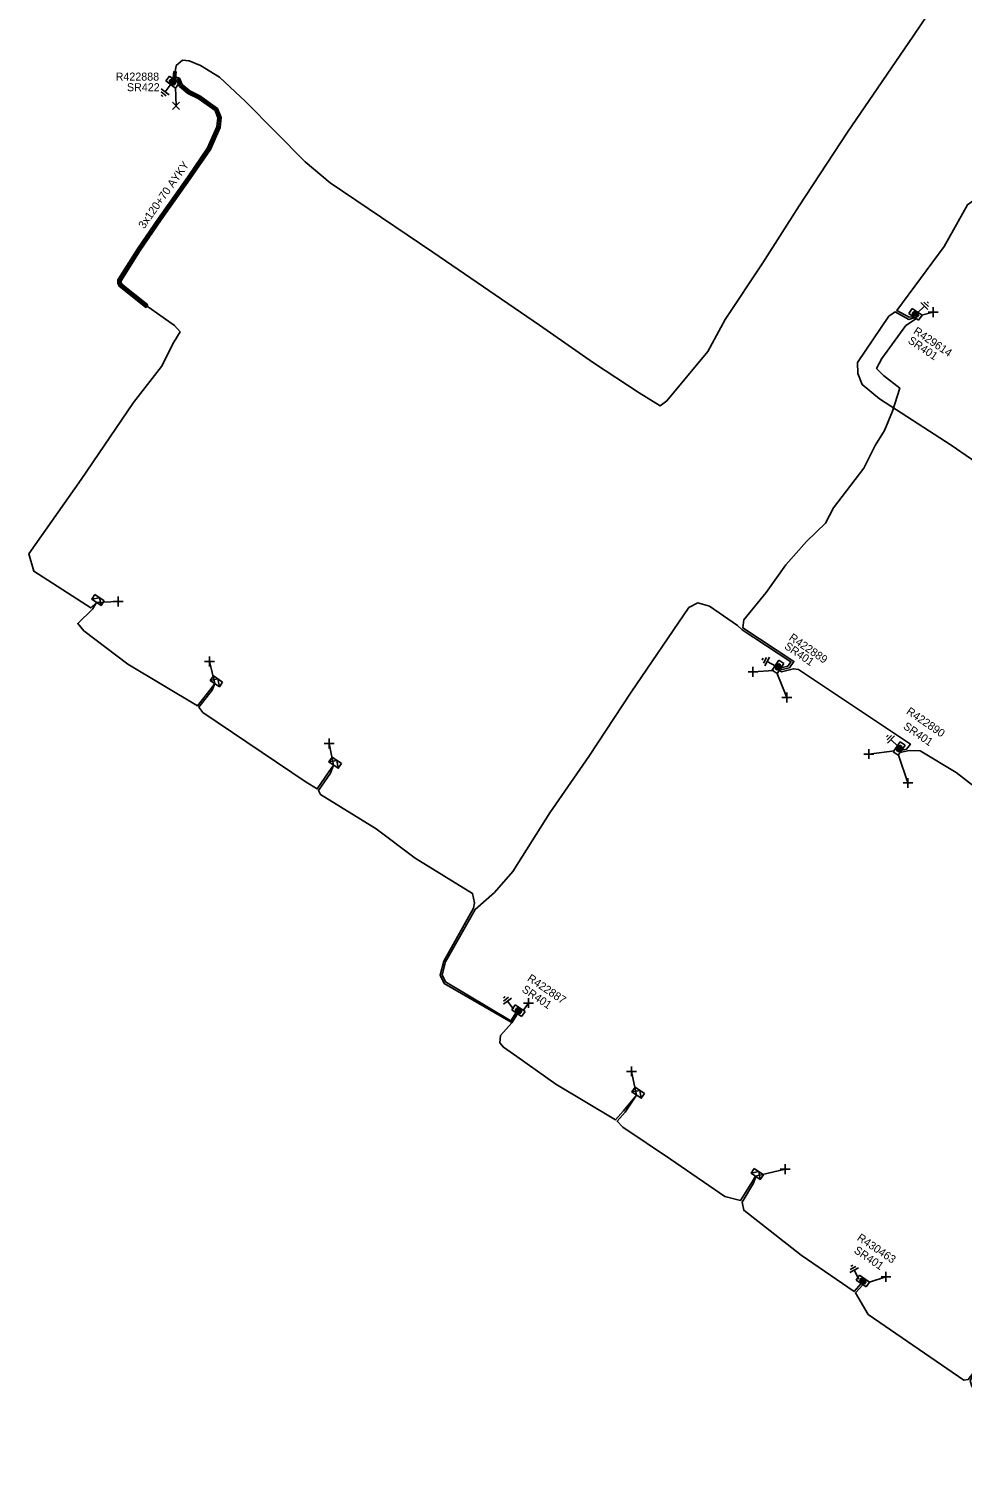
# Model space of a CAD drawing. Extents: x -540247 to -537390, y -1183887 to -1180355.
# Drawn here: x -539012.1 to -538895.4, y -1181471.3 to -1181292.1 of the extents above; entities that cross this region are included whole.
import ezdxf

# ---------------------------------------------------------------- set-up
doc = ezdxf.new("R2010")
doc.units = 0
for name, color, linetype in [('Vrstva 1', 7, 'Continuous'), ('Vrstva 14', 7, 'Continuous'), ('Vrstva 15', 7, 'Continuous'), ('Vrstva 20', 7, 'Continuous'), ('Vrstva 28', 7, 'Continuous'), ('Vrstva 29', 7, 'Continuous'), ('Vrstva 30', 7, 'Continuous'), ('Vrstva 31', 7, 'Continuous'), ('Vrstva 34', 7, 'Continuous'), ('Vrstva 5', 7, 'Continuous'), ('Vrstva 59', 7, 'Continuous'), ('Vrstva 6', 7, 'Continuous'), ('Vrstva 8', 7, 'Continuous'), ('Vrstva 9', 7, 'Continuous')]:
    doc.layers.add(name, color=color, linetype=linetype)

# ---------------------------------------------------------------- blocks, each defined once
blk = doc.blocks.new('NN800')
at = {"layer": 'Vrstva 1'}
for points in [[(-0.44, 0.44), (0.44, -0.44)], [(-0.44, -0.44), (0.44, 0.44)]]:
    blk.add_lwpolyline(points, dxfattribs=at)
blk = doc.blocks.new('NN620')
at = {"layer": 'Vrstva 8'}
for points in [[(0.75, 0), (-0.75, 0)], [(-0.75, 0), (-0.75, -0.75)], [(0.75, -0.75), (0.75, 0)], [(-0.75, -0.75), (0.75, -0.75)], [(0.37, -0.18), (-0.38, -0.18)], [(-0.38, -0.18), (-0.38, -0.56)], [(-0.38, -0.56), (0.37, -0.56)], [(0.32, -0.23), (-0.33, -0.23)], [(-0.33, -0.23), (-0.33, -0.51)], [(-0.33, -0.51), (0.32, -0.51)], [(0.27, -0.27), (-0.28, -0.27)], [(-0.28, -0.27), (-0.28, -0.46)], [(-0.28, -0.46), (0.27, -0.46)], [(0.23, -0.32), (-0.23, -0.32)], [(-0.23, -0.32), (-0.23, -0.42)], [(-0.23, -0.42), (0.23, -0.42)], [(-0.19, -0.37), (0.19, -0.37)], [(0.23, -0.42), (0.23, -0.32)], [(0.27, -0.46), (0.27, -0.27)], [(0.32, -0.51), (0.32, -0.23)], [(0.37, -0.56), (0.37, -0.18)]]:
    blk.add_lwpolyline(points, dxfattribs=at)
blk = doc.blocks.new('NN630')
at = {"layer": 'Vrstva 9'}
for points in [[(0, -0.7), (-0.7, 0)], [(-0.7, -0.7), (-0.7, 0), (0.7, 0), (0.7, -0.7)], [(-0.7, -0.7), (0.7, -0.7)], [(0, -0.7), (0.7, 0)]]:
    blk.add_lwpolyline(points, dxfattribs=at)
blk = doc.blocks.new('NN810')
at = {"layer": 'Vrstva 14'}
for points in [[(0, -0.64), (0, -1.89)], [(0.63, -1.89), (-0.62, -1.89)], [(0.39, -2.2), (-0.4, -2.2)], [(0, -2.52), (-0.12, -2.52)], [(0.14, -2.52), (0, -2.52)]]:
    blk.add_lwpolyline(points, dxfattribs=at)

msp = doc.modelspace()

# ---------------------------------------------------------------- linework, layer by layer
at = {"layer": 'Vrstva 20'}
for points in [[(-538997.22, -1181326.62), (-538997.46, -1181326.94), (-539000.79, -1181324.29), (-539000.97, -1181323.91), (-539000.96, -1181323.49), (-538998.52, -1181319.62), (-538995.88, -1181315.78), (-538993.45, -1181312.31), (-538992.23, -1181310.63), (-538989.75, -1181306.99), (-538988.59, -1181304.36), (-538988.46, -1181303.25), (-538988.82, -1181302.34), (-538990.93, -1181300.81), (-538992.21, -1181300.19), (-538993.25, -1181299.31), (-538993.57, -1181298.62), (-538993.64, -1181298.6), (-538993.69, -1181298.66), (-538994.01, -1181298.42), (-538993.79, -1181298.13), (-538993.27, -1181298.3), (-538992.93, -1181299.07), (-538991.99, -1181299.85), (-538990.73, -1181300.47), (-538988.5, -1181302.08), (-538988.06, -1181303.19), (-538988.19, -1181304.46), (-538989.39, -1181307.19), (-538991.91, -1181310.87), (-538993.13, -1181312.55), (-538995.56, -1181316), (-538998.18, -1181319.84), (-539000.56, -1181323.61), (-539000.57, -1181323.83), (-539000.47, -1181324.03)], [(-538994.13, -1181298.34), (-538994.05, -1181298.22), (-538993.97, -1181297.45), (-538993.67, -1181297.49), (-538993.76, -1181298.33), (-538993.89, -1181298.51)]]:
    msp.add_lwpolyline(points, close=True, dxfattribs=at)
at = {"layer": 'Vrstva 5'}
for points in [[(-538994.01, -1181298.42), (-538993.91, -1181298.28), (-538993.82, -1181297.47), (-538993.66, -1181296.71), (-538992.9, -1181296.02), (-538992.04, -1181296.12), (-538990.64, -1181296.68), (-538988.25, -1181298.17), (-538985.02, -1181301.2), (-538977.55, -1181308.74), (-538974.45, -1181311.38), (-538961.61, -1181320.01), (-538948.29, -1181329.14), (-538941.55, -1181333.87), (-538935.84, -1181337.61), (-538933.19, -1181339.22), (-538932.35, -1181338.61), (-538927.24, -1181332.45), (-538925.06, -1181328.44), (-538920.37, -1181321.36), (-538915.82, -1181314.24), (-538909.77, -1181305.05), (-538901.59, -1181293.05), (-538896.72, -1181285.79)], [(-538876.6, -1181288.05), (-538880.49, -1181293.95), (-538882.71, -1181296.89), (-538882.46, -1181297.61), (-538881.24, -1181298.27), (-538881.1, -1181298.04), (-538881.16, -1181298.59), (-538882.67, -1181297.78), (-538883.26, -1181297.76), (-538887.18, -1181303.5), (-538893.05, -1181311.89), (-538893.15, -1181312.81), (-538891.79, -1181313.26), (-538891.39, -1181313.1), (-538891.78, -1181313.52), (-538893.29, -1181313.03), (-538894.78, -1181314.11), (-538897.72, -1181319.32), (-538903.63, -1181327.31), (-538902.07, -1181328.17), (-538901.52, -1181328.1)], [(-538951.13, -1181415.15), (-538951.82, -1181416.26), (-538960.21, -1181411.42), (-538960.69, -1181410.38), (-538960.25, -1181408.62), (-538956.52, -1181402.03), (-538956.39, -1181401.37), (-538956.63, -1181400.18), (-538963.82, -1181395.78), (-538968.69, -1181392.11), (-538975.65, -1181387.81), (-538975.88, -1181387.32), (-538974.41, -1181385.15), (-538974.01, -1181384.13), (-538974.6, -1181384.98), (-538976.05, -1181387.12), (-538977.45, -1181386.28), (-538990.36, -1181377.56), (-538990.84, -1181376.89), (-538989.17, -1181374.77), (-538988.85, -1181373.95), (-538989.32, -1181374.57), (-538991.02, -1181376.73), (-538999.73, -1181371.54), (-539005.21, -1181367.35), (-539005.98, -1181366.43), (-539004.15, -1181364.66), (-539003.64, -1181363.8), (-539004.35, -1181364.5), (-539011.47, -1181359.91), (-539012.11, -1181357.73), (-539005.57, -1181348.42), (-538999, -1181338.81), (-538995.51, -1181334.33), (-538993.97, -1181331.26), (-538993.18, -1181329.98), (-538993.89, -1181329.18), (-538997.14, -1181326.92), (-538997.34, -1181326.78), (-539000.63, -1181324.16), (-539000.77, -1181323.87), (-539000.76, -1181323.55), (-538998.35, -1181319.73), (-538995.72, -1181315.89), (-538993.29, -1181312.43), (-538992.07, -1181310.75), (-538989.57, -1181307.09), (-538988.39, -1181304.41), (-538988.26, -1181303.22), (-538988.66, -1181302.21), (-538990.83, -1181300.64), (-538992.1, -1181300.02), (-538993.09, -1181299.19), (-538993.42, -1181298.46), (-538993.72, -1181298.36), (-538993.85, -1181298.54)], [(-538918.17, -1181372.07), (-538917.99, -1181372.2), (-538917.05, -1181371.97), (-538916.48, -1181371.17), (-538922.88, -1181366.99), (-538922.74, -1181366), (-538919.96, -1181362.56), (-538917.5, -1181359.1), (-538914.93, -1181356.19), (-538912.52, -1181353.91), (-538911.52, -1181351.97), (-538907.74, -1181347.01), (-538906.34, -1181344.2), (-538905.18, -1181342.3), (-538904.16, -1181339.91), (-538903.26, -1181337.02), (-538905.31, -1181335.43), (-538906.16, -1181334.56), (-538905.52, -1181333.32), (-538902.49, -1181329.2), (-538901.18, -1181328.32)], [(-538901.35, -1181328.21), (-538902.12, -1181328.43), (-538903.82, -1181327.49), (-538904.61, -1181328.02), (-538908.52, -1181333.8), (-538908.51, -1181335.18), (-538907.95, -1181336.57), (-538905.78, -1181338.37), (-538896.83, -1181344.13), (-538889.35, -1181349.32), (-538885.03, -1181352.64), (-538880.81, -1181353.87), (-538878.18, -1181356.19), (-538876.84, -1181356.64), (-538875.59, -1181355.58), (-538871.8, -1181350.1), (-538870.87, -1181350.27), (-538869.79, -1181350.73), (-538869.04, -1181350.41)], [(-538951.23, -1181415.08), (-538951.86, -1181416.09), (-538960.01, -1181411.24), (-538960.43, -1181410.36), (-538960.01, -1181408.72), (-538956.31, -1181402.17), (-538953.92, -1181400.07), (-538951.63, -1181397.45), (-538946.98, -1181390.11), (-538942.12, -1181383.05), (-538936.81, -1181375.02), (-538929.62, -1181364.45), (-538928.48, -1181363.86), (-538927.02, -1181364.29), (-538923.53, -1181366.7), (-538922.97, -1181367.23), (-538916.86, -1181371.22), (-538917.25, -1181371.77), (-538917.94, -1181371.93), (-538918.02, -1181371.87)], [(-538918.31, -1181372.28), (-538918.04, -1181372.47), (-538916.55, -1181372.1), (-538915.9, -1181372.18), (-538901.93, -1181381.51), (-538902.41, -1181382.13), (-538903.02, -1181382.27)], [(-538903.23, -1181382.58), (-538902.08, -1181382.3), (-538900.71, -1181382.36), (-538896.23, -1181385.05), (-538890.51, -1181389.46), (-538887.34, -1181391.55), (-538887.48, -1181392.31), (-538888.12, -1181392.32)], [(-538908.07, -1181448.94), (-538908.97, -1181449.93), (-538915.6, -1181445.37), (-538922.76, -1181439.78), (-538922.97, -1181438.76), (-538921.52, -1181436.37), (-538921.25, -1181435.55), (-538921.27, -1181435.52), (-538921.71, -1181436.23), (-538923.14, -1181438.55), (-538925.13, -1181438.06), (-538931.91, -1181433.37), (-538937.87, -1181429.37), (-538938.59, -1181428.63), (-538937.57, -1181427.5), (-538936.15, -1181425.38), (-538936.15, -1181425.37), (-538937.76, -1181427.34), (-538938.79, -1181428.46), (-538946.25, -1181424.02), (-538951.11, -1181420.54), (-538952.79, -1181419.39), (-538953.23, -1181418.85), (-538953.15, -1181417.93), (-538951.72, -1181416.33), (-538951.02, -1181415.22)], [(-538878.34, -1181469.21), (-538879.88, -1181471.28), (-538880.11, -1181471.25), (-538894.24, -1181461.79), (-538894.47, -1181461.03), (-538893.25, -1181459.04), (-538893.26, -1181459.03), (-538894.71, -1181460.92), (-538895.25, -1181461.02), (-538907.2, -1181452.8), (-538908.8, -1181450.11), (-538907.86, -1181449.08)]]:
    msp.add_lwpolyline(points, dxfattribs=at)
at = {"layer": 'Vrstva 59'}
for points in [[(-538993.78, -1181299.4), (-538993.69, -1181301.74)], [(-538900.56, -1181327.91), (-538899.08, -1181327.51)], [(-539003.64, -1181363.8), (-539000.91, -1181363.69)], [(-538988.85, -1181373.95), (-538989.52, -1181371.18)], [(-538919.01, -1181372.32), (-538921.6, -1181372.49)], [(-538918.62, -1181372.61), (-538917.38, -1181375.69)], [(-538974.01, -1181384.13), (-538974.55, -1181381.44)], [(-538903.91, -1181382.35), (-538907.12, -1181382.75)], [(-538903.46, -1181382.78), (-538902.23, -1181386.37)], [(-538950.32, -1181414.81), (-538949.67, -1181413.87)], [(-538936.15, -1181425.37), (-538936.79, -1181422.41)], [(-538921.27, -1181435.52), (-538917.57, -1181434.62)], [(-538907.16, -1181448.8), (-538904.98, -1181448.11)]]:
    msp.add_lwpolyline(points, dxfattribs=at)

# ---------------------------------------------------------------- block references
at = {"layer": 'Vrstva 15'}
for p, rotation in [((-538993.93, -1181298.48), -36.79985391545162), ((-538901.52, -1181328.1), 135), ((-538918.17, -1181372.07), -118.04657767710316), ((-538903.02, -1181382.27), -135), ((-538951.13, -1181415.15), -142.69803611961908), ((-538908.07, -1181448.94), -152.22659712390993)]:
    msp.add_blockref('NN810', p, dxfattribs=dict(at, rotation=rotation))
at = {"layer": 'Vrstva 28'}
for p, rotation in [((-538993.93, -1181298.48), -36.797268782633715), ((-538901.52, -1181328.1), 145.967763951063), ((-538918.17, -1181372.07), -124.4581195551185), ((-538903.02, -1181382.27), -124.45811942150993), ((-538951.13, -1181415.15), 145.91936669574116), ((-538908.07, -1181448.94), 145.91936665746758)]:
    msp.add_blockref('NN620', p, dxfattribs=dict(at, rotation=rotation))
at = {"layer": 'Vrstva 31'}
for p, rotation in [((-539003.64, -1181363.8), 145.64415554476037), ((-538988.85, -1181373.95), 145.6441555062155), ((-538974.01, -1181384.13), 145.64415561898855), ((-538936.15, -1181425.37), 145.64415554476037), ((-538921.27, -1181435.52), 145.64415561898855)]:
    msp.add_blockref('NN630', p, dxfattribs=dict(at, rotation=rotation))
at = {"layer": 'Vrstva 34'}
msp.add_blockref('NN800', (-538993.69, -1181301.74), dxfattribs=at)
for p, rotation in [((-538899.08, -1181327.51), 45.000000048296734), ((-539000.91, -1181363.69), 45), ((-538989.52, -1181371.18), 45), ((-538921.6, -1181372.49), 44.99999995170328), ((-538917.38, -1181375.69), 44.99999995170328), ((-538974.55, -1181381.44), 45), ((-538907.12, -1181382.75), 45), ((-538902.23, -1181386.37), 45), ((-538949.67, -1181413.87), 45), ((-538936.79, -1181422.41), 44.99999995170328), ((-538917.57, -1181434.62), 45), ((-538904.98, -1181448.11), 45)]:
    msp.add_blockref('NN800', p, dxfattribs=dict(at, rotation=rotation))

# ---------------------------------------------------------------- texts
at = {"layer": 'Vrstva 29'}
for s, rotation, p in [('R422888', 359.951, (-539001.24, -1181298.58)), ('R429614', 325.968, (-538901.65, -1181330.12)), ('R422889', 325.542, (-538917.19, -1181368.42)), ('R422890', 325.542, (-538902.53, -1181377.64)), ('R422887', 325.919, (-538949.89, -1181411.01)), ('R430463', 325.919, (-538908.68, -1181443.43))]:
    msp.add_text(s, height=1, rotation=rotation, dxfattribs=at).set_placement(p)
at = {"layer": 'Vrstva 30'}
for s, rotation, p in [('SR422', 359.995, (-538999.83, -1181299.91)), ('SR401', 325.968, (-538902.33, -1181331.29)), ('SR401', 325.542, (-538917.77, -1181369.49)), ('SR401', 325.542, (-538902.92, -1181379.5)), ('SR401', 325.919, (-538950.57, -1181412.38)), ('SR401', 325.919, (-538909.08, -1181445))]:
    msp.add_text(s, height=1, rotation=rotation, dxfattribs=at).set_placement(p)
at = {"layer": 'Vrstva 6'}
msp.add_text('3x120+70 AYKY', height=1, rotation=54.919, dxfattribs=at).set_placement((-538997.67, -1181317.18))

doc.saveas('drawing.dxf')
